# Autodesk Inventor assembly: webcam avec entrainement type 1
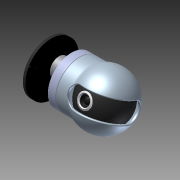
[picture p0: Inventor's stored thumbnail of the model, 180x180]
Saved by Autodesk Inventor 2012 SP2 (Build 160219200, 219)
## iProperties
Created: 2013-08
Part Number: webcam avec entrainement type 1
Document SubType Name: Assembly
Designer: hilarion
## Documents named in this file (9)
- L:\STI2D\Ressources eleves\ITEC\Tsti2d Fichot 2013-14\Webcam motorisee\webcam avec entrainement type 1.iam
- L:\STI2D\Ressources eleves\ITEC\Tsti2d Fichot 2013-14\Webcam motorisee\Base.ipt
- L:\STI2D\Ressources eleves\ITEC\Tsti2d Fichot 2013-14\Webcam motorisee\Moto-reducteur vertical.ipt
- L:\STI2D\Ressources eleves\ITEC\Tsti2d Fichot 2013-14\Webcam motorisee\Socle.ipt
- L:\STI2D\Ressources eleves\ITEC\Tsti2d Fichot 2013-14\Webcam motorisee\Semelle.ipt
- L:\STI2D\Ressources eleves\ITEC\Tsti2d Fichot 2013-14\Webcam motorisee\cache_réducteur.ipt
- L:\STI2D\Ressources eleves\ITEC\Tsti2d Fichot 2013-14\Webcam motorisee\sortie_moteur.iam
- L:\STI2D\Ressources eleves\ITEC\Tsti2d Fichot 2013-14\Webcam motorisee\Pignon_étagé.iam
- L:\STI2D\Ressources eleves\ITEC\Tsti2d Fichot 2013-14\Webcam motorisee\tête Webcam motorisee.iam
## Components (8 placed, 8 different names)
1. Base:1 — Logement:4, Logement:5, Logement:6
2. Moto-reducteur vertical:1 — Logement:2
3. Socle:1 — Logement:5
4. Semelle:1 — Logement:6
5. cache_réducteur:1 — Logement:1, Logement:3, Logement:4
6. sortie_moteur:1 [sub-assembly] — Logement:2, Rotation:1
7. Pignon_étagé:1 [sub-assembly] — Logement:3, Rotation:1, Rotation:2
8. tête Webcam motorisee:1 [sub-assembly] — Logement:1, Rotation:2
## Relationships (8: Insert 6, RelateRotation 2)
- Logement:1 [Insert]: cache_réducteur:1 ↔ tête Webcam motorisee:1
- Logement:2 [Insert]: Moto-reducteur vertical:1 ↔ sortie_moteur:1
- Logement:3 [Insert]: cache_réducteur:1 ↔ Pignon_étagé:1
- Rotation:1 [RelateRotation]: sortie_moteur:1 ↔ Pignon_étagé:1
- Rotation:2 [RelateRotation]: Pignon_étagé:1 ↔ tête Webcam motorisee:1
- Logement:4 [Insert]: Base:1 ↔ cache_réducteur:1
- Logement:5 [Insert]: Base:1 ↔ Socle:1
- Logement:6 [Insert]: Base:1 ↔ Semelle:1
